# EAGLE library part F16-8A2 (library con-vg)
CONNECTOR female, 16 pins + 8 high current, type C
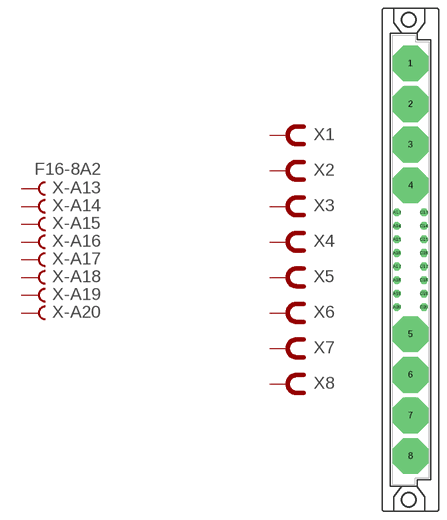
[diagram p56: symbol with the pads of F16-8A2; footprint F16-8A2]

Designator prefix X; gates 1=FEM-HIGHCUR 2=FEM-HIGHCUR 3=FEM-HIGHCUR 4=FEM-HIGHCUR 5=FEM-HIGHCUR 6=FEM-HIGHCUR 7=FEM-HIGHCUR 8=FEM-HIGHCUR -A13=FVAL -A14=FEM -A15=FEM -A16=FEM -A17=FEM -A18=FEM -A19=FEM -A20=FEM -C13=FVAL -C14=FEM -C15=FEM -C16=FEM -C17=FEM -C18=FEM -C19=FEM -C20=FEM

## F16-8A2  [F16-8A2]
1  1:B  pas
2  2:B  pas
3  3:B  pas
4  4:B  pas
5  5:B  pas
6  6:B  pas
7  7:B  pas
8  8:B  pas
A13  -A13:B  pas
A14  -A14:B  pas
A15  -A15:B  pas
A16  -A16:B  pas
A17  -A17:B  pas
A18  -A18:B  pas
A19  -A19:B  pas
A20  -A20:B  pas
C13  -C13:B  pas
C14  -C14:B  pas
C15  -C15:B  pas
C16  -C16:B  pas
C17  -C17:B  pas
C18  -C18:B  pas
C19  -C19:B  pas
C20  -C20:B  pas

## Footprint F16-8A2 (pad centres in mm)
CONNECTOR female, 16 pins + 8 high current, type C
drill 5.7 octagon: 1 0,36.83; 2 0,29.21; 3 0,21.59; 4 0,13.97; 5 0,-13.97; 6 0,-21.59; 7 0,-29.21; 8 0,-36.83
drill 0.914 octagon: A13 -2.54,8.89; A14 -2.54,6.35; A15 -2.54,3.81; A16 -2.54,1.27; A17 -2.54,-1.27; A18 -2.54,-3.81; A19 -2.54,-6.35; A20 -2.54,-8.89; C13 2.54,8.89; C14 2.54,6.35; C15 2.54,3.81; C16 2.54,1.27; C17 2.54,-1.27; C18 2.54,-3.81; C19 2.54,-6.35; C20 2.54,-8.89
hole 2.794 at -0.305,45.009
hole 2.794 at -0.305,-45.009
